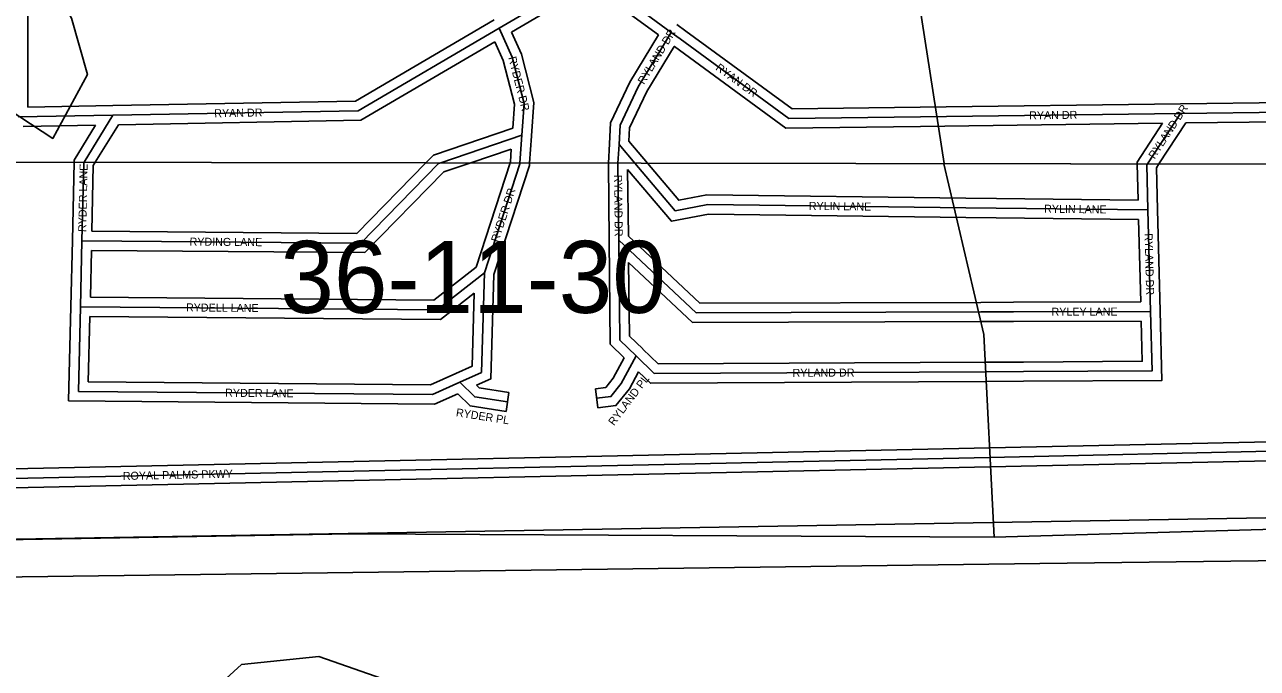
# Model space of a CAD drawing. Extents: x 457167 to 656239, y 1787309 to 1969297.
# Drawn here: x 580690 to 584541, y 1876691 to 1878702 of the extents above; entities that cross this region are included whole.
import ezdxf

# ---------------------------------------------------------------- set-up
doc = ezdxf.new("R2010")
doc.units = 0
for name, color, linetype in [('Level 1', 7, 'Continuous'), ('Level 2', 7, 'Continuous'), ('Level 31', 7, 'Continuous'), ('Level 32', 7, 'Continuous'), ('Level 34', 7, 'Continuous'), ('Level 5', 7, 'Continuous'), ('Level 55', 7, 'Continuous'), ('Level 63', 7, 'Continuous'), ('Level 7', 7, 'Continuous')]:
    doc.layers.add(name, color=color, linetype=linetype)

msp = doc.modelspace()

# ---------------------------------------------------------------- linework, layer by layer
at = {"layer": 'Level 1'}
msp.add_line((584949.895, 1877168.15), (580044.647, 1877084.268), dxfattribs=at)
at = {"layer": 'Level 31'}
for p, q in [((582172.273, 1878691.366), (582461.144, 1878860.974)), ((582461.144, 1878860.974), (582710.191, 1878678.296)), ((582710.191, 1878678.296), (582737.509, 1878658.242)), ((580669.86, 1878414.395), (580966.044, 1878419.611)), ((580966.044, 1878419.611), (580875.985, 1878272.706)), ((583488.437, 1878414.58), (584300.944, 1878424.996)), ((584300.944, 1878424.996), (584197.476, 1878267.37)), ((584300.944, 1878424.996), (584654.389, 1878429.767)), ((581990.691, 1878270.915), (582243.504, 1878356.677)), ((582243.504, 1878356.677), (582237.463, 1878270.518)), ((582543.781, 1878270.026), (582546.939, 1878328.437)), ((582596.385, 1878269.942), (582546.939, 1878328.437)), ((581990.633, 1878270.915), (581990.634, 1878270.915)), ((581990.634, 1878270.915), (581990.635, 1878270.915)), ((581990.635, 1878270.915), (581990.635, 1878270.915)), ((581990.635, 1878270.915), (581990.636, 1878270.915)), ((581990.636, 1878270.915), (581990.637, 1878270.915)), ((581990.637, 1878270.915), (581990.638, 1878270.915)), ((581990.638, 1878270.915), (581990.639, 1878270.915)), ((581990.639, 1878270.915), (581990.64, 1878270.915)), ((581990.64, 1878270.915), (581990.64, 1878270.915)), ((581990.64, 1878270.915), (581990.641, 1878270.915)), ((581990.641, 1878270.915), (581990.642, 1878270.915)), ((581990.642, 1878270.915), (581990.643, 1878270.915)), ((581990.643, 1878270.915), (581990.644, 1878270.915)), ((581990.644, 1878270.915), (581990.645, 1878270.915)), ((581990.645, 1878270.915), (581990.645, 1878270.915)), ((581990.645, 1878270.915), (581990.646, 1878270.915)), ((581990.646, 1878270.915), (581990.647, 1878270.915)), ((581990.647, 1878270.915), (581990.648, 1878270.915)), ((581990.648, 1878270.915), (581990.649, 1878270.915)), ((581990.649, 1878270.915), (581990.65, 1878270.915)), ((581990.65, 1878270.915), (581990.65, 1878270.915)), ((581990.65, 1878270.915), (581990.651, 1878270.915)), ((581990.651, 1878270.915), (581990.652, 1878270.915)), ((581990.652, 1878270.915), (581990.653, 1878270.915)), ((581990.653, 1878270.915), (581990.654, 1878270.915)), ((581990.654, 1878270.915), (581990.655, 1878270.915)), ((581990.655, 1878270.915), (581990.655, 1878270.915)), ((581990.655, 1878270.915), (581990.656, 1878270.915)), ((581990.656, 1878270.915), (581990.657, 1878270.915)), ((581990.657, 1878270.915), (581990.658, 1878270.915)), ((581990.658, 1878270.915), (581990.659, 1878270.915)), ((581990.659, 1878270.915), (581990.66, 1878270.915)), ((581990.66, 1878270.915), (581990.66, 1878270.915)), ((581990.66, 1878270.915), (581990.661, 1878270.915)), ((581990.661, 1878270.915), (581990.662, 1878270.915)), ((581990.662, 1878270.915), (581990.663, 1878270.915)), ((581990.663, 1878270.915), (581990.664, 1878270.915)), ((581990.664, 1878270.915), (581990.665, 1878270.915)), ((581990.665, 1878270.915), (581990.665, 1878270.915)), ((581990.665, 1878270.915), (581990.666, 1878270.915)), ((581990.666, 1878270.915), (581990.667, 1878270.915)), ((581990.667, 1878270.915), (581990.668, 1878270.915)), ((581990.668, 1878270.915), (581990.669, 1878270.915)), ((581990.669, 1878270.915), (581990.67, 1878270.915)), ((581990.67, 1878270.915), (581990.67, 1878270.915)), ((581990.67, 1878270.915), (581990.671, 1878270.915)), ((581990.671, 1878270.915), (581990.672, 1878270.915)), ((581990.672, 1878270.915), (581990.673, 1878270.915)), ((581990.673, 1878270.915), (581990.674, 1878270.915)), ((581990.674, 1878270.915), (581990.675, 1878270.915)), ((581990.675, 1878270.915), (581990.675, 1878270.915)), ((581990.675, 1878270.915), (581990.676, 1878270.915)), ((581990.676, 1878270.915), (581990.677, 1878270.915)), ((581990.677, 1878270.915), (581990.678, 1878270.915)), ((581990.678, 1878270.915), (581990.679, 1878270.915)), ((581990.679, 1878270.915), (581990.68, 1878270.915)), ((581990.68, 1878270.915), (581990.68, 1878270.915)), ((581990.68, 1878270.915), (581990.681, 1878270.915)), ((581990.681, 1878270.915), (581990.682, 1878270.915)), ((581990.682, 1878270.915), (581990.683, 1878270.915)), ((581990.683, 1878270.915), (581990.684, 1878270.915)), ((581990.684, 1878270.915), (581990.685, 1878270.915)), ((581990.685, 1878270.915), (581990.685, 1878270.915)), ((581990.685, 1878270.915), (581990.686, 1878270.915)), ((581990.686, 1878270.915), (581990.687, 1878270.915)), ((581990.687, 1878270.915), (581990.688, 1878270.915)), ((581990.688, 1878270.915), (581990.689, 1878270.915)), ((581990.689, 1878270.915), (581990.69, 1878270.915)), ((581990.69, 1878270.915), (581990.69, 1878270.915)), ((581990.69, 1878270.915), (581990.691, 1878270.915)), ((581990.691, 1878270.915), (581990.692, 1878270.915)), ((582126.534, 1877927.094), (582237.285, 1878267.962)), ((582237.464, 1878270.518), (582237.285, 1878267.962)), ((582543.637, 1878267.352), (582543.782, 1878270.026)), ((582543.637, 1878267.352), (582546.346, 1878028.803)), ((582823.972, 1878140.252), (583630.403, 1878130.301)), ((583630.403, 1878130.301), (583725.52, 1878129.025)), ((583725.52, 1878129.025), (584199.2, 1878123.739)), ((584207.493, 1877806.634), (584199.2, 1878123.739)), ((580869.495, 1878027.443), (580864.941, 1877821.272)), ((580864.941, 1877821.272), (580858.36, 1877556.559)), ((583676.85, 1877804.758), (583779.288, 1877804.921)), ((583779.288, 1877804.921), (584207.493, 1877806.634)), ((583692.074, 1877617.821), (583810.101, 1877618.317)), ((583705.55, 1877350.523), (586097.05, 1877402.291)), ((578604.695, 1877240.843), (583705.55, 1877350.523))]:
    msp.add_line(p, q, dxfattribs=at)
for points in [[(580966.044, 1878419.611), (581732.433, 1878433.701), (582172.273, 1878691.366)], [(582172.273, 1878691.366), (582213.449, 1878600.739), (582250.382, 1878456.301), (582243.504, 1878356.677)], [(582546.939, 1878328.437), (582550.238, 1878388.067), (582607.102, 1878508.319), (582710.191, 1878678.296)], [(582737.509, 1878658.242), (583077.729, 1878409.206), (583488.437, 1878414.58)], [(580875.986, 1878272.706), (580874.76, 1878270.704), (580869.495, 1878027.443)], [(580869.495, 1878027.443), (581740.195, 1878020.231), (581983.422, 1878268.47), (581990.633, 1878270.915)], [(582823.972, 1878140.252), (582722.135, 1878121.181), (582596.386, 1878269.942)], [(584197.477, 1878267.37), (584195.336, 1878264.109), (584199.2, 1878123.739)], [(582546.346, 1878028.803), (582549.545, 1877716.798), (582600.348, 1877667.607)], [(582546.346, 1878028.803), (582787.992, 1877802.143), (583676.85, 1877804.758)], [(580864.941, 1877821.272), (581978.69, 1877811.391), (582126.534, 1877927.094)], [(582050.136, 1877585.066), (582117.324, 1877615.841), (582126.534, 1877927.094)], [(583810.101, 1877618.317), (584211.905, 1877620.808), (584207.493, 1877806.634)], [(582600.348, 1877667.607), (582554.048, 1877581.154), (582521.518, 1877540.491), (582477.287, 1877535.125)], [(582600.348, 1877667.607), (582657.184, 1877612.221), (583692.074, 1877617.821)], [(580858.36, 1877556.559), (581964.165, 1877546.694), (582050.136, 1877585.066)], [(582050.136, 1877585.066), (582096.175, 1877539.52), (582198.581, 1877523.68)]]:
    msp.add_lwpolyline(points, dxfattribs=at)
at = {"layer": 'Level 32'}
for p, q in [((580699.886, 1878444.928), (580700.287, 1878938.371)), ((582210.764, 1878679.176), (582459.316, 1878825.11)), ((582459.316, 1878825.109), (582670.29, 1878670.357)), ((582727.944, 1878702.481), (582755.263, 1878682.426)), ((582718.851, 1878634.722), (582719.757, 1878634.057)), ((580699.886, 1878444.928), (580965.515, 1878449.606)), ((583488.053, 1878444.578), (584300.56, 1878454.995)), ((584300.54, 1878454.993), (584653.985, 1878459.765)), ((583488.823, 1878384.581), (584244.892, 1878394.273)), ((584317.283, 1878395.212), (584233.324, 1878267.313)), ((584317.282, 1878395.212), (584614.201, 1878399.221)), ((580685.955, 1878384.671), (580911.875, 1878388.651)), ((580983.029, 1878389.916), (580911.14, 1878272.649)), ((582273.431, 1878354.578), (582267.535, 1878270.471)), ((582513.74, 1878270.075), (582516.983, 1878330.057)), ((582635.722, 1878269.879), (582577.554, 1878338.693)), ((582083.599, 1878270.766), (582210.424, 1878313.777)), ((582210.424, 1878313.776), (582207.614, 1878273.731)), ((580844.797, 1878272.756), (580839.501, 1878028.092)), ((582100.832, 1877945.075), (582206.588, 1878270.568)), ((582156.395, 1877921.911), (582266.955, 1878262.191)), ((582206.587, 1878270.568), (582207.614, 1878273.731)), ((582267.536, 1878270.471), (582266.955, 1878262.191)), ((582513.629, 1878267.992), (582513.741, 1878270.075)), ((582513.629, 1878267.992), (582516.348, 1878028.462)), ((582573.835, 1878250.147), (582576.2, 1878041.932)), ((584165.233, 1878267.421), (584168.354, 1878154.084)), ((582821.372, 1878170.286), (583630.773, 1878160.3)), ((583630.805, 1878160.299), (583725.923, 1878159.022)), ((583725.923, 1878159.022), (584168.354, 1878154.084)), ((584237.483, 1877807.417), (584229.19, 1878124.522)), ((582826.575, 1878110.216), (583630.033, 1878100.303)), ((583630, 1878100.304), (583725.117, 1878099.026)), ((583725.185, 1878099.026), (584169.966, 1878094.062)), ((584176.702, 1877836.511), (584169.966, 1878094.062)), ((580839.502, 1878028.106), (580834.948, 1877821.935)), ((580898.836, 1877997.198), (580895.606, 1877851.001)), ((580834.95, 1877822.018), (580827.612, 1877526.831)), ((583676.802, 1877834.757), (583779.24, 1877834.921)), ((583779.169, 1877834.921), (584176.702, 1877836.511)), ((580894.2, 1877791.009), (580889.11, 1877586.286)), ((583676.899, 1877774.757), (583779.337, 1877774.921)), ((583779.409, 1877774.921), (584178.199, 1877776.516)), ((583691.947, 1877647.82), (583809.975, 1877648.317)), ((583692.2, 1877587.82), (583810.228, 1877588.317)), ((582203.167, 1877553.327), (582193.995, 1877494.031)), ((582480.9, 1877505.342), (582473.673, 1877564.906)), ((583704.901, 1877380.516), (586057.951, 1877431.451)), ((578633.935, 1877271.478), (583704.905, 1877380.516)), ((583706.2, 1877320.529), (586055.92, 1877371.392)), ((578635.465, 1877211.497), (583706.195, 1877320.529))]:
    msp.add_line(p, q, dxfattribs=at)
for points in [[(580965.491, 1878449.606), (581724.037, 1878463.552), (582157.108, 1878717.253)], [(582210.764, 1878679.176), (582241.859, 1878610.736), (582280.644, 1878459.052), (582273.433, 1878354.611)], [(582516.984, 1878330.095), (582520.607, 1878395.586), (582580.644, 1878522.548), (582670.29, 1878670.357)], [(582755.229, 1878682.451), (583087.359, 1878439.335), (583488.044, 1878444.578)], [(580983.03, 1878389.916), (581740.828, 1878403.849), (582158.725, 1878648.66)], [(582158.726, 1878648.659), (582185.039, 1878590.741), (582220.12, 1878453.549), (582214.952, 1878378.671)], [(582577.554, 1878338.693), (582579.868, 1878380.549), (582633.559, 1878494.089), (582718.852, 1878634.722)], [(582719.789, 1878634.034), (583068.099, 1878379.076), (583488.83, 1878384.581)], [(584244.892, 1878394.273), (584165.087, 1878272.698), (584165.232, 1878267.421)], [(580911.876, 1878388.651), (580844.941, 1878279.466), (580844.796, 1878272.756)], [(581943.889, 1878270.991), (581967.004, 1878294.581), (582214.952, 1878378.671)], [(580898.836, 1877997.198), (581752.698, 1877990.125), (581999.839, 1878242.358), (582083.6, 1878270.766)], [(580911.141, 1878272.649), (580904.578, 1878261.942), (580900.147, 1878057.19)], [(580900.147, 1878057.19), (581727.69, 1878050.336), (581943.89, 1878270.991)], [(582826.575, 1878110.216), (582710.495, 1878088.48), (582573.835, 1878250.147)], [(582821.371, 1878170.286), (582733.775, 1878153.882), (582635.723, 1878269.879)], [(584233.325, 1878267.313), (584225.585, 1878255.52), (584229.189, 1878124.564)], [(582516.347, 1878028.496), (582519.675, 1877703.961), (582563.211, 1877661.806)], [(582576.2, 1878041.932), (582799.823, 1877832.179), (583676.761, 1877834.758)], [(580895.606, 1877851.001), (581968.465, 1877841.482), (582100.832, 1877945.075)], [(582577.066, 1877958.856), (582579.415, 1877729.636), (582621.216, 1877689.16)], [(582577.066, 1877958.856), (582776.161, 1877772.108), (583676.939, 1877774.757)], [(582102.093, 1877575.866), (582146.76, 1877596.326), (582156.395, 1877921.911)], [(580894.2, 1877791.01), (581988.917, 1877781.298), (582094.655, 1877864.048)], [(582037.643, 1877612.341), (582087.887, 1877635.356), (582094.655, 1877864.048)], [(583810.287, 1877588.318), (584242.62, 1877590.998), (584237.485, 1877807.346)], [(583809.915, 1877648.317), (584181.188, 1877650.618), (584178.2, 1877776.515)], [(582621.285, 1877689.092), (582669.316, 1877642.288), (583691.91, 1877647.82)], [(582563.211, 1877661.806), (582528.902, 1877597.745), (582505.745, 1877568.797), (582473.673, 1877564.906)], [(580889.11, 1877586.286), (581957.9, 1877576.751), (582037.643, 1877612.341)], [(582607.97, 1877618.291), (582579.195, 1877564.563), (582537.292, 1877512.186), (582480.9, 1877505.342)], [(582607.97, 1877618.291), (582645.051, 1877582.155), (583692.236, 1877587.821)], [(580827.612, 1877526.831), (581970.428, 1877516.636), (582043.625, 1877549.306)], [(582043.626, 1877549.306), (582081.985, 1877511.358), (582193.995, 1877494.031)], [(582102.093, 1877575.866), (582110.365, 1877567.682), (582203.167, 1877553.327)]]:
    msp.add_lwpolyline(points, dxfattribs=at)
at = {"layer": 'Level 5'}
for points in [[(583562.149, 1878269.148), (583396.553, 1879336.403), (583447.127, 1879836.515), (583614.304, 1880261.506), (583581.417, 1880695.026), (583548.136, 1880753.418), (583506.643, 1880953.552), (583373.754, 1881395.512), (583182.861, 1882212.671), (583149.579, 1882262.722), (583116.457, 1882462.827), (583049.864, 1882554.629)], [(583718.942, 1877100.851), (583686.276, 1877734.441), (583561.79, 1878268.098)], [(583718.942, 1877100.851), (586528.362, 1877181.246), (598932.909, 1877301.462), (599299.903, 1877484.467)], [(576708.032, 1877024.934), (581709.894, 1877111.311), (583718.942, 1877100.851)]]:
    msp.add_lwpolyline(points, dxfattribs=at)
at = {"layer": 'Level 55'}
for p, q in [((586112.288, 1877047.354), (583861.107, 1877018.585)), ((583861.107, 1877018.585), (579674.329, 1876964.804))]:
    msp.add_line(p, q, dxfattribs=at)
at = {"layer": 'Level 63'}
for points in [[(576708.289, 1878279.4), (616473.709, 1878215.526), (616521.962, 1923670.374), (576805.545, 1923734.416), (576708.289, 1878279.4)], [(576611.219, 1832825.663), (616425.226, 1832761.92), (616473.71, 1878215.526), (576708.29, 1878279.4), (576611.219, 1832825.663)]]:
    msp.add_lwpolyline(points, dxfattribs=at)
at = {"layer": 'Level 7'}
for points in [[(580394.719, 1878597.659), (580777.928, 1878347.186), (580886.497, 1878547.121), (580836.674, 1878722.255), (580770.111, 1878847.357), (580370.321, 1879189.573)], [(581175.75, 1876528.359), (581367.682, 1876703.193), (581609.465, 1876727.975), (581851.12, 1876644.355)]]:
    msp.add_lwpolyline(points, dxfattribs=at)

# ---------------------------------------------------------------- texts
at = {"layer": 'Level 2'}
msp.add_text('36-11-30', height=225, dxfattribs=at).set_placement((581489.011, 1877801.951))
at = {"layer": 'Level 34'}
for s, height, rotation, p in [('RYLAND DR', 25, 58.76295, (582624.989, 1878513.71)), ('RYDER DR', 25, 284.342875, (582200.846, 1878599.573)), ('RYAN DR', 25, 323.796075, (582846.483, 1878562.984)), ('RYAN DR', 25, 1.052936, (581282.864, 1878412.933)), ('RYAN DR', 25, 0.734178, (583828.243, 1878406.436)), ('RYLAND DR', 25, 56.717261, (584219.723, 1878280.724)), ('RYDER LANE', 24.9992, 88.7596, (580882.579, 1878054.341)), ('RYLAND DR', 25, 270.649989, (582531.523, 1878233.442)), ('RYDER DR', 25, 72.000119, (582170.146, 1878020.876)), ('RYLIN LANE', 25, 359.2928, (583139.638, 1878123.857)), ('RYLIN LANE', 25, 359.360333, (583874.824, 1878114.858)), ('RYLAND DR', 25, 271.497611, (584188.615, 1878050.342)), ('RYDING LANE', 25, 359.525092, (581205.532, 1878012.16)), ('RYDELL LANE', 25, 359.491367, (581194.333, 1877806.639)), ('RYLEY LANE', 25, 0.228767, (583898.008, 1877792.897)), ('RYLAND DR', 25, 0.309686, (583089.185, 1877602.059)), ('RYLAND PL', 25, 52.927825, (582531.097, 1877447.749)), ('RYDER LANE', 25, 359.488531, (581316.666, 1877539.97)), ('RYDER PL', 25, 351.206633, (582036.456, 1877479.313)), ('ROYAL PALMS PKWY', 25, 1.231503, (580997.16, 1877279.785))]:
    msp.add_text(s, height=height, rotation=rotation, dxfattribs=at).set_placement(p)

doc.saveas('drawing.dxf')
